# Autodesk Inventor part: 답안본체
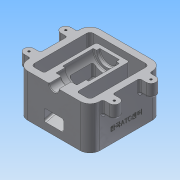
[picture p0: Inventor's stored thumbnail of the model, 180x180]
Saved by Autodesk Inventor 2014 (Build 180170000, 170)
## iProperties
Created: 2018-01
Part Number: 답안본체
Material: 알루미늄 6061
Document SubType Name: Modeling
Designer: NET
Density: 2.71 g/cm^3
Appearance: 알루미늄 - 평지
Mass: 998.903 g
Surface Area: 834.406 cm^2
Volume: 368.599 cm^3
Author: NET
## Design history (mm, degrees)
sketch "스케치1"
  geometry: L1 (55, -55)-(-55, -55); L2 (-55, -55)-(-55, 55); L3 (-55, 55)-(55, 55); L4 (55, 55)-(55, -55); L5 (55, -55)-(-55, 55); L6 (-55, -55)-(55, 55); 1 further point
  constraints: 12 end point, 2 midpoint, 2 parallel, 1 horizontal, 1 perpendicular
  dimensions: "d0" = 110 distance of L2.end L3.end; "d1" = 110 distance of L3.end L1.start
extrude "돌출1" new body sketch "스케치1" distance "d2" = 65; taper "d3" = 0 deg
sketch "스케치2"
  geometry: L1 (55, -55)-(55, 55) reference; L2 (55, 55)-(-55, 55) reference; L3 (45, -45)-(-45, -45); L4 (-45, -45)-(-45, 45); L5 (-45, 45)-(45, 45); L6 (45, 45)-(45, -45); L7 (45, -45)-(-45, 45); L8 (-45, -45)-(45, 45); 1 further point
  constraints: 12 end point, 2 midpoint, 2 parallel, 1 horizontal, 1 perpendicular
  dimensions: "d4" = 10 distance between parallel lines of L2 L5; "d5" = 10 distance between parallel lines of L1 L6
extrude "돌출2" cut sketch "스케치2" stored distance "d6" = 65; taper "d7" = 0 deg
sketch "스케치3"
  geometry: L1 (-55, -55)-(55, -55) reference; L2 (55, -55)-(55, 55) reference; L3 (-55, 55)-(-55, -55) reference; L4 (-65, -35.5)-(-55, -35.5); L5 (-65, -20.5)-(-55, -20.5); L6 (-65, 20.5)-(-55, 20.5); L7 (-65, 35.5)-(-55, 35.5); L8 (65, 35.5)-(55, 35.5); L9 (55, 55)-(55, -55) reference; L10 (65, 20.5)-(55, 20.5); L11 (65, -20.5)-(55, -20.5); L12 (65, -35.5)-(55, -35.5); A1 r 7.5 centre (-65, -28) between (-65, -20.5) and (-65, -35.5); A2 r 7.5 centre (-65, 28) between (-65, 35.5) and (-65, 20.5); A3 r 7.5 centre (65, -28) between (65, -35.5) and (65, -20.5); A4 r 7.5 centre (65, 28) between (65, 20.5) and (65, 35.5); 1 further point
  constraints: 16 end point, 8 point on circle, 8 point on line, 8 tangent, 6 perpendicular, 4 centre point, 3 equal radius, 2 parallel
  dimensions: "d8" = 56 distance of A2.centre A1.centre; "d9" = 27 distance from line of L1 A1.centre; "d10" = 27 distance from line of L1 A3.centre; "d11" = 56 distance of A4.centre A3.centre; "d12" = 10 distance from line of L2 A4.centre; "d13" = 10 distance from line of L2 A3.centre; "d14" = 15 diameter of A4; "d15" = 10 distance from line of L3 A2.centre; "d16" = 10 distance from line of L3 A1.centre
extrude "돌출3" join sketch "스케치3" distance "d17" = 20; taper "d18" = 0 deg
fillet "모깎기1" dims "d19" = 3
fillet "모깎기2" dims "d20" = 3
fillet "모깎기3" dims "d21" = 3
fillet "모깎기4" dims "d22" = 3
sketch "스케치4"
  geometry: A1 r 7.5 centre (65, -28) between (65, -35.5) and (65, -20.5) reference; A2 r 7.5 centre (65, 28) between (65, 20.5) and (65, 35.5) reference; A3 r 7.5 centre (-65, 28) between (-65, 35.5) and (-65, 20.5) reference; A4 r 7.5 centre (-65, -28) between (-65, -20.5) and (-65, -35.5) reference; 5 further points
  constraints: 4 coincident
hole "구멍1" sketch "스케치4" at (-65, 28), (65, 28), (65, -28), (-65, -28) diameter "d23" = 3.242; stored, may be unused: countersink angle "d27" = 90 deg, drill point angle "d29" = 118 deg; dims "d24" = 9, "d25" = 4, "d26" = 2, "d28" = 11
node "작업 평면1"
sketch "스케치5"
  geometry: L1 (110, 65)-(110, 0) reference; L2 (110, 0)-(100, 0) reference; L3 (100, 0)-(100, 65) reference; L4 (100, 65)-(110, 65) reference; L5 (0, 0)-(0, 65) reference; L6 (0, 65)-(10, 65) reference; L7 (10, 65)-(10, 0) reference; L8 (10, 0)-(0, 0) reference; L9 (10, 65)-(90, 65); L10 (90, 65)-(90, 30); L11 (90, 30)-(10, 8.564); L12 (10, 65)-(10, 8.564); L13 (16.5, 65)-(0, 65) reference; L14 (100, 0)-(10, 0) reference; 1 further point
  constraints: 8 end point, 2 perpendicular, 1 parallel, 1 point on line
  dimensions: "d30" = 30 distance from line of L14 L10.end; "d31" = 20 distance between parallel lines of L1 L10; "d32" = 105 deg angle of L7 L11
extrude "돌출4" join sketch "스케치5" stored distance "d33" = 50; taper "d34" = 0 deg
sketch "스케치6"
  geometry: L1 (-55, -55)-(55, -55) reference; L2 (55, 55)-(-55, 55) reference; L3 (0, -55)-(0, 55); L4 (-7.5, -55)-(-7.5, -36); L5 (-7.5, -36)-(-16, -36); L6 (-16, -36)-(-16, -22); L7 (-16, -22)-(-20, -22); L8 (-20, -22)-(-20, 25); L9 (-20, 25)-(-15, 25); L10 (-15, 25)-(-15, 30); L11 (-15, 30)-(0, 30); 1 further point
  constraints: 18 end point, 7 parallel, 2 midpoint, 2 point on line, 1 perpendicular
  dimensions: "d35" = 15 diameter of L4 L3; "d36" = 19 distance of L4.start L4.end; "d37" = 14 distance of L5.end L6.end; "d38" = 47 distance of L7.end L8.end; "d39" = 5 distance of L9.end L10.end; "d40" = 32 diameter of L6 L3; "d41" = 40 diameter of L8 L3; "d42" = 30 diameter of L10 L3
revolve "회전1" sketch "스케치6" stored, may be unused: angle "d43" = 90 deg
sketch "스케치7"
  geometry: L1 (-20, -22)-(-20, 25) reference; L2 (-20, 25)-(-15, 25) reference; L3 (-15, -17)-(15, -17); L4 (15, -17)-(15, 20); L5 (15, 20)-(-15, 20); L6 (-15, 20)-(-15, -17); 1 further point
  constraints: 8 end point, 2 parallel, 1 horizontal, 1 perpendicular
  dimensions: "d44" = 30 distance between parallel lines of L4 L6; "d45" = 37 distance of L5.end L3.start; "d46" = 5 distance between parallel lines of L2 L5; "d47" = 5 distance between parallel lines of L1 L6
extrude "돌출5" cut sketch "스케치7" distance "d48" = 30; taper "d49" = 0 deg
sketch "스케치8"
  geometry: L1 (30, 50)-(30, 65) reference; L2 (30, 65)-(35, 65) reference; L3 (35, 65)-(35, 30) reference; L4 (35, 30)-(-45, 8.564) reference; L5 (-45, 8.564)-(-45, 0) reference; L6 (-45, 0)-(-55, 0) reference; L7 (-55, 0)-(-55, 57.5) reference; L8 (-55, 57.5)-(-36, 57.5) reference; L9 (-36, 57.5)-(-36, 49) reference; L10 (-36, 49)-(-22, 49) reference; L11 (-22, 49)-(-22, 45) reference; L12 (-22, 45)-(-17, 45) reference; L13 (-17, 45)-(-17, 35) reference; L14 (-17, 35)-(20, 35) reference; L15 (20, 35)-(20, 45) reference; L16 (20, 45)-(25, 45) reference; L17 (25, 45)-(25, 50) reference; L18 (25, 50)-(30, 50) reference; L19 (45, 65)-(55, 65) reference; L20 (55, 65)-(55, 0) reference; L21 (55, 0)-(45, 0) reference; L22 (45, 0)-(45, 65) reference; L23 (-55, 11.061)-(20, 31.157); L24 (20, 31.157)-(20, 35); L25 (-55, 29.061)-(-17, 39.243); L26 (-17, 39.243)-(-17, 35); 1 further point
  constraints: 8 end point, 4 parallel, 2 point on line
  dimensions: "d50" = 5 distance between parallel lines of L4 L23; "d51" = 18 distance of L23.start L25.start
extrude "돌출6" cut sketch "스케치8" stored distance "d52" = 30; taper "d53" = 0 deg
fillet "모깎기5" dims "d54" = 1
chamfer "모따기1" distance "d55" = 1; stored, may be unused: second distance "d56" = 2, angle "d57" = 45 deg
fillet "모깎기6" dims "d58" = 3
fillet "모깎기7" dims "d59" = 3
fillet "모깎기8" dims "d60" = 3
fillet "모깎기9" dims "d61" = 3
fillet "모깎기10" dims "d62" = 3
fillet "모깎기11" dims "d63" = 3
fillet "모깎기12" dims "d64" = 15
fillet "모깎기13" dims "d65" = 5
sketch "스케치9"
  geometry: L1 (65, 57.5)-(65, -22.5) reference; L2 (0, -37.5)-(65, -37.5) reference; 2 further points
  constraints: 1 other
  dimensions: "d66" = 55 distance from line of point (45, 17.5) L2; "d67" = 20 distance from line of L1 point (45, 17.5)
feature "엠보싱1" sketch "스케치9" dims "d0" = 110, "d1" = 110, "d68" = 0.5, "d69" = 0
node "솔리드1"
node "절단 모서리 투영1"
node "절단 모서리 투영2"
